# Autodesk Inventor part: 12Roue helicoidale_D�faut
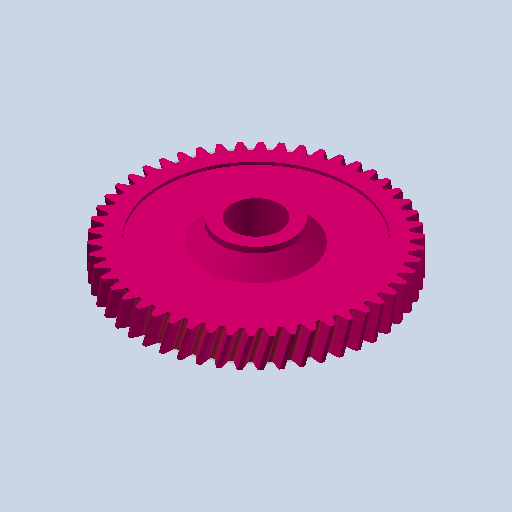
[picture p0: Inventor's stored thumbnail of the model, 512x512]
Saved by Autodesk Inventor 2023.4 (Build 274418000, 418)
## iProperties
Created: 2011-01
Part Number: 12Roue helicoidale_D�faut
Document SubType Name: Modeling
Designer: eric
Density: 1 g/cm^3
Mass: 54.2193 g
Surface Area: 182.103 cm^2
Volume: 54.2193 cm^3
Material: Générique
Appearance: 255,0,128_1
Author: eric
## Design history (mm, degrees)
feature "Base1"
sketch "Esquisse1"
  geometry: C1 r 34 at (0, 0) reference; C2 r 40 at (0, 0)
  constraints: 1 centre point, 1 coincident
  dimensions: "d0" = 80 diameter of C2
feature "SrfExtrusion1" sketch "Esquisse1" dims "d1" = 10, "d2" = 0
node "Corps solides"
node "Corps surfaciques"
body "Srf1"
node "Solide1"
